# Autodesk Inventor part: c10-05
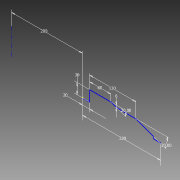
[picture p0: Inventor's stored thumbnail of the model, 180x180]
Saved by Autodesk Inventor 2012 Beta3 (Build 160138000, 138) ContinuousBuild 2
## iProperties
Created: 2011-01
Part Number: c10-05
Material: Aluminum-6061
Document SubType Name: Sheet Metal
Designer: Beta-8540w
Density: 2.71 g/cm^3
Sheet Metal Rule: Aluminum - 3.4mm
Author: Beta-8540w
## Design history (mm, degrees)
sketch "Sketch1"
  geometry: L1 (0, 0)-(20, 0); L2 (20, 0)-(20, 30); L3 (20, 30)-(80, 30); L4 (96.485, 24)-(150, 24); L5 (150, 24)-(200, 5.801); L6 (200, 5.801)-(200, 0); L7 (200, 0)-(220, 0); L8 (-200, 0)-(-200, 73.265); L9 (80, 30)-(96.485, 24); 1 further point
  constraints: 18 end point, 3 collinear, 3 parallel, 2 perpendicular, 1 coincident, 1 horizontal, 1 horizontal alignment
  dimensions: "d5" = 20 distance of L1.start L1.end; "d6" = 30 distance of L1.end L2.end; "d7" = 60 distance of L2.end L3.end; "d9" = 220 distance of L7.end point (0, 0); "d11" = 20 deg angle of L5 L4; "d12" = 200 distance from line of point (0, 0) L8; "d13" = 6 vertical distance of L3.end L4.start; "d14" = 130 distance from line of L4.end L2; "d15" = 20 deg angle of L9 L3
body "Solid1"
other parameters: "Thickness" = 3.4 (derived), "BendRadius" = 2 (derived), "BendReliefWidth" = 3.4 (= Thickness), "BendReliefDepth" = 1.7 (= 0.5 x Thickness), "CornerReliefSize" = 13.6 (= 4 x Thickness), "SeamGap" = 0.01, "MinimumRemnant" = 6.8 (= 2 x Thickness), "TransitionRadius" = 2 (= BendRadius), "JacobiRadiusSize" = 2 (= BendRadius), "GapSize" = 3.4 (= Thickness), "d4" = 2 (= BendRadius)
